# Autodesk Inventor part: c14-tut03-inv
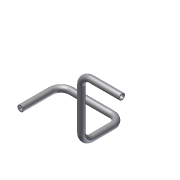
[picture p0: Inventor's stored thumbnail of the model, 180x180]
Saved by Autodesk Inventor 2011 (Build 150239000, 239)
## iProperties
Created: 2010-04
Part Number: c14-tut03-inv
Document SubType Name: Modeling
Designer: CADSoft
Density: 1 g/cm^3
Author: CADSoft
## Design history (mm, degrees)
sketch "Sketch1"
  geometry: L1 (0, 0)-(0, 40); L2 (0, 40)-(60, 40); L3 (60, 40)-(60, 0)
  constraints: 6 end point, 2 perpendicular, 1 vertical
  dimensions: "d0" = 40 distance of L1.start L1.end; "d2" = 60 distance of L1.end L2.end; "d4" = 40 distance of L2.end L3.end
workplane "Work Plane1"
sketch "Sketch2"
  geometry: L1 (0, 0)-(0, 60); L2 (0, 0)-(60, 0); L3 (0, 60)-(40, 60); 1 further point
  constraints: 6 end point, 2 perpendicular, 1 horizontal, 1 vertical
  dimensions: "d5" = 60 distance of L1.start L1.end; "d6" = 90 deg angle of L2 L1 (derived); "d7" = 40 distance of L1.end L3.end; "d8" = 90 deg angle of L1 L3 (derived)
sketch "3D Sketch1" dims "d9" = 10, "d11" = 10 (= d9)
  geometry: L1 through (10, 10) direction (-1, 0); L2 through (0, 50) direction (0, 1); 15 other entities
  constraints: 2 horizontal, 2 vertical
  dimensions: "d10" = 10 distance of the line from the sketch origin of L1 (= d9); "d12" = 10 dimension on L2 (= d9)
workplane "Work Plane2"
sketch "Sketch3"
  geometry: C1 r 3 at (0, 0); C2 r 2 at (0, 0); 1 further point
  constraints: 2 centre point, 2 coincident
  dimensions: "d13" = 4 diameter of C2; "d14" = 6 diameter of C1
sweep "Sweep1" sketch "Sketch3" dims "d15" = 0
body "Solid1"
